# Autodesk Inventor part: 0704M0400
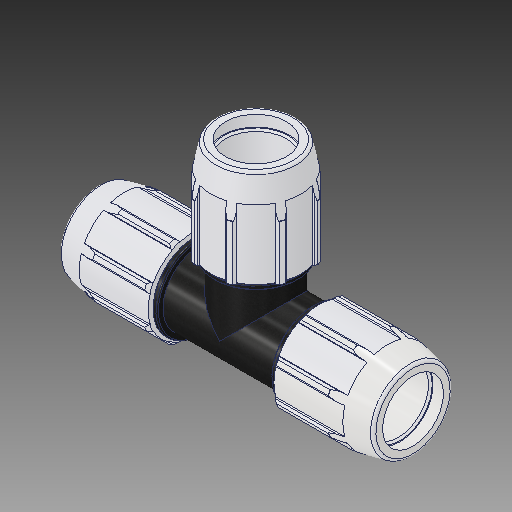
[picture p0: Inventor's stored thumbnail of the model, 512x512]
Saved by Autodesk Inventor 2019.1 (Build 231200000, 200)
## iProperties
Created: 2017-02
Part Number: 0704M0400
Material: PVC-Piping
Description: PLASSON TEE 4'' - 4'' - 4''
Document SubType Name: Modeling
Designer: KIM
Mass: 92.6774 g
Surface Area: 199.44 cm^2
Volume: 66.1981 cm^3
Density: 1.4 g/cm^3
Appearance: PTFE
Author: KIM
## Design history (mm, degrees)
derived "0704M0.ipt"
feature "Solid1::0704M0.ipt"
tag "TaggingFeature1"
body "Solid1"
other parameters: "d2" = 114.1, "d4" = 24.48983, "d5" = 73.4695, "d7" = 181.102, "d11" = 9.79593, "d13" = 120 deg, "d14" = 148.33, "d15" = 12 deg, "d16" = 157.55874, "d18" = 5.705, "d19" = 35 deg, "d20" = 17.5 deg, "d21" = 168.42486, "d23" = 0, "d25" = 360 deg, "d27" = 3.62204, "d33" = 2.282, "d42" = 102.8573, "d43" = 5.43306, "d46" = 3.423, "d63" = 196.088, "d67" = 135.8265, "d76" = 114.1, "d77" = 181.102, "d78" = 12 deg, "d79" = 293.878, "d80" = 120 deg, "d81" = 148.33, "d82" = 24.48983, "d85" = 135.8265, "d86" = 157.55874, "d87" = 9.79593, "d88" = 9.79593, "d89" = 73.4695, "d90" = 102.8573, "d96" = 8.39651, "d98" = 168.42486, "d99" = 35 deg, "d100" = 17.5 deg, "d102" = 0, "d103" = 3.62204, "d107" = 360 deg, "d109" = 3.423, "d112" = 5.705, "d118" = 360 deg, "d121" = 0, "d128" = 588.01, "d131" = 102.69, "d132" = 102.69, "d133" = 196.088, "d134" = 3.92176, "d135" = 9.79593, "d152" = 0, "d154" = 0, "d156" = 0, "d158" = 0, "d_" = 114.1, "E_" = 181.102, "A_" = 293.878, "l_" = 196.088, "H_" = 588.01
